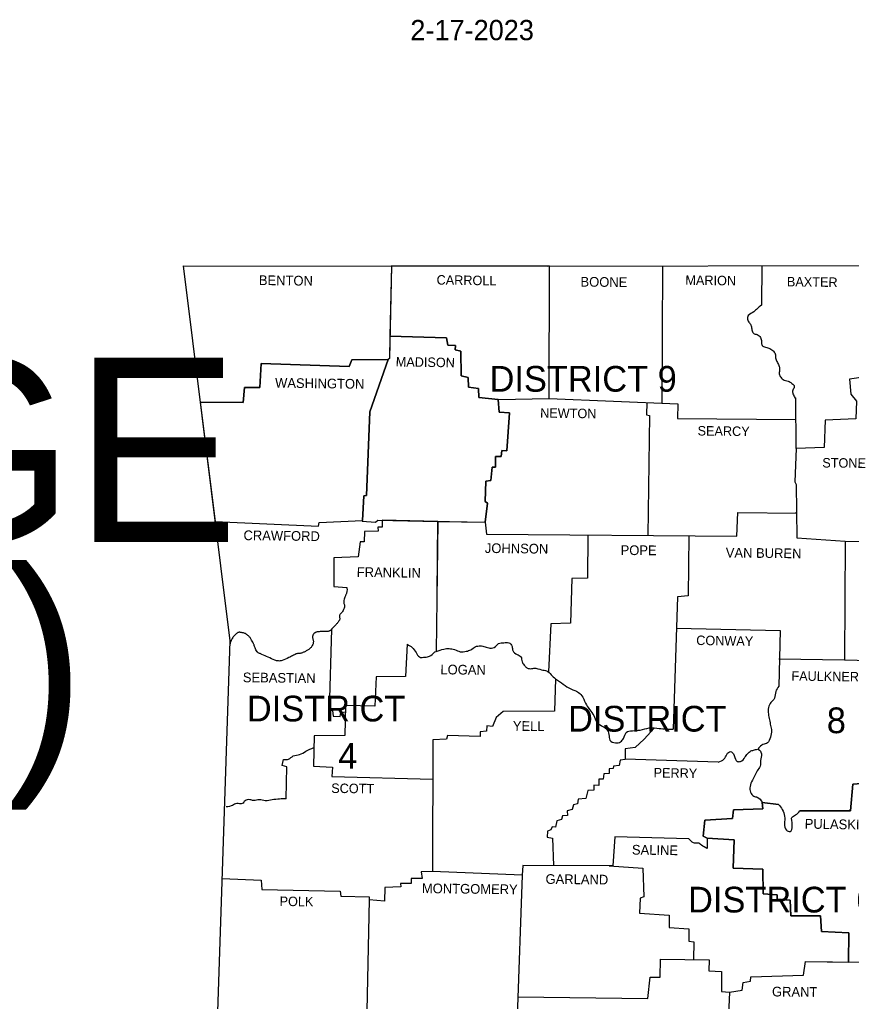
# Model space of a CAD drawing. Extents: x -24122 to 24238, y -8840 to 11381.
# Drawn here: x 10036 to 13643, y 7122 to 11381 of the extents above; entities that cross this region are included whole.
import ezdxf

# ---------------------------------------------------------------- set-up
doc = ezdxf.new("R2010")
doc.units = 0
for name, color, linetype in [('R_Annotation', 7, 'Continuous'), ('R_Border', 7, 'Continuous'), ('R_Grid', 7, 'Continuous'), ('R_No Plot', 7, 'Continuous'), ('S_AREA_CALC', 7, 'Continuous')]:
    doc.layers.add(name, color=color, linetype=linetype)

msp = doc.modelspace()

# ---------------------------------------------------------------- linework, layer by layer
at = {"layer": 'R_Annotation'}
for p, q in [((11648.6, 10312.4), (11641.8, 10007.9)), ((12332.4, 9737.7), (12334.4, 10312)), ((11641.8, 10007.9), (11639.7, 9910.9)), ((11925.3, 9948), (11926.3, 9967.6)), ((11634.8, 9906), (11555.5, 9679)), ((11639.7, 9910.9), (11634.8, 9906)), ((11010.5, 9784.6), (11005.6, 9720.1)), ((11005.6, 9720.1), (10819.1, 9721.1)), ((10819.1, 9721.1), (10883.4, 9204.6)), ((12111.1, 9733), (12028.1, 9741.6)), ((13398.8, 9740.6), (13402.7, 9740.6)), ((11555.5, 9679), (11539.9, 9316)), ((11522.4, 9208.5), (11528.1, 9315)), ((10883.4, 9204.6), (11332.4, 9183.9)), ((11332.4, 9183.9), (11334.4, 9199.6)), ((11334.4, 9199.6), (11522.4, 9208.5)), ((11522.4, 9208.5), (11522.2, 9205.4)), ((11522.2, 9205.4), (11580, 9200.5)), ((11846.2, 8890.8), (11850, 9204.4)), ((11850, 9204.5), (11850, 9204.4)), ((11850, 9204.4), (12055.5, 9200.5)), ((13241.3, 8220.2), (13240.3, 8215.3)), ((13257, 7986.3), (13257, 7984.4)), ((13018.2, 7830.8), (13018.2, 7785.8)), ((13169.9, 7170.3), (13173.8, 7203.6)), ((13173.8, 7203.6), (13206.1, 7209.5)), ((13206.1, 7209.5), (13208, 7229)), ((13115.1, 7162.5), (13169.9, 7170.3))]:
    msp.add_line(p, q, dxfattribs=at)
for points in [[(12334.4, 10312), (12327.5, 10312), (11648.6, 10312.4)], [(11641.8, 10007.9), (11887.2, 9999.9), (11893.1, 9968.6), (11926.3, 9967.6), (11925.3, 9948), (11948.8, 9942.2), (11950.8, 9835.5), (11981.1, 9828.7), (11983.1, 9786.6), (12026.1, 9780.7), (12028.1, 9741.6), (12111.1, 9733), (12113.2, 9732.8), (12332.4, 9737.7)], [(11926.3, 9967.6), (11893.1, 9968.6), (11887.2, 9999.9), (11641.8, 10007.9)], [(11950.8, 9835.5), (11948.8, 9942.2), (11925.3, 9948)], [(11634.8, 9906), (11477.2, 9905), (11465.5, 9875.6), (11083.9, 9889.3), (11078, 9784.6), (11010.5, 9784.6)], [(11528.1, 9315), (11539.9, 9316), (11555.5, 9679), (11634.8, 9906)], [(11983.1, 9786.6), (11981.1, 9828.7), (11950.8, 9835.5)], [(12028.1, 9741.6), (12026.1, 9780.7), (11983.1, 9786.6)], [(12055.5, 9200.5), (12065.3, 9283.7), (12055.5, 9290.6), (12058.4, 9378.6), (12079.9, 9381.5), (12084.8, 9439.3), (12099.5, 9440.2), (12100.5, 9485.3), (12124, 9485.3), (12127.9, 9511.7), (12148.4, 9510.7), (12160.2, 9675.1), (12115.2, 9678), (12111.1, 9733)], [(11539.9, 9316), (11528.1, 9315), (11522.4, 9208.5)], [(11580, 9200.5), (11588.8, 9209.3), (11850, 9204.5)], [(11850, 9204.4), (11608.3, 9209)], [(13419.4, 7948.2), (13639.5, 7949.2), (13649.3, 8064.6), (13780.4, 8074.4)], [(13018.2, 7830.8), (13000.6, 7839.6), (13007.5, 7908.1), (13127.8, 7914.9), (13131.7, 7953.1), (13259.9, 7958), (13257, 7984.4), (13327.4, 7976.6)], [(12938, 7826.9), (12618.1, 7836.6), (12609.3, 7710.4), (12593.6, 7710.5)], [(13631.7, 7292.5), (13632.7, 7419.8), (13513.3, 7425.7), (13509.4, 7493.2), (13380.2, 7493.2), (13378.3, 7561.7), (13321.5, 7565.6), (13321.5, 7584.2), (13260.9, 7589.1), (13258.9, 7695.8), (13130.7, 7700.6), (13134.7, 7822.9), (13018.2, 7830.8)], [(13631.7, 7292.5), (13632.7, 7419.8), (13513.3, 7425.7), (13509.4, 7493.2), (13380.2, 7493.2), (13378.3, 7561.7), (13321.5, 7565.6), (13321.5, 7584.2), (13260.9, 7589.1), (13258.9, 7695.8), (13130.7, 7700.6), (13134.7, 7822.9), (13018.2, 7830.8)], [(12593.6, 7710.5), (12739.4, 7699.7), (12743.3, 7576.4), (12726.7, 7570.5), (12724.7, 7505), (12852.9, 7496.2), (12852.9, 7442.3), (12938, 7437.5), (12939, 7383.6), (12959.5, 7380.7), (12958.5, 7303.4)], [(12958.5, 7303.4), (13027, 7302.4), (13025.1, 7255.5), (13079.9, 7251.6), (13079.9, 7165.5), (13115.1, 7162.5)], [(13208, 7229), (13436, 7235.9), (13444.8, 7295.6), (13631.7, 7292.5)]]:
    msp.add_lwpolyline(points, dxfattribs=at)
for points in [[(13327.4, 7976.6), (13344, 7955), (13353.8, 7925.7), (13353.8, 7892.4), (13361.7, 7865), (13377.3, 7859.1), (13387.1, 7882.6), (13385.1, 7906.1), (13385.1, 7919.8), (13401.8, 7931.5), (13419.4, 7948.2)], [(13018.2, 7785.8), (12992.8, 7800.4), (12978.1, 7809.2), (12962.5, 7808.3), (12949.7, 7816.1), (12938, 7826.9)]]:
    msp.add_spline(points, degree=3, dxfattribs=at)
at = {"layer": 'R_No Plot'}
msp.add_line((11639.7, 9910.9), (11634.8, 9906), dxfattribs=at)
at = {"layer": 'S_AREA_CALC'}
for p, q in [((11836.3, 8638.9), (11843.2, 8639.9)), ((12329.1, 8551.2), (12329.1, 8548.9)), ((11311.9, 8223.1), (11312.3, 8223.3))]:
    msp.add_line(p, q, dxfattribs=at)
for points in [[(10745.4, 10313), (12327.5, 10312), (13715.8, 10314.9), (15353.7, 10340.4), (16112.9, 10358)], [(10745.4, 10313), (10947.9, 8686.9), (10859.9, 6032.5)], [(11648.6, 10312.4), (11639.7, 9910.9)], [(11641.8, 10007.9), (11887.2, 9999.9), (11893.1, 9968.6), (11926.3, 9967.6), (11925.3, 9948), (11948.8, 9942.2), (11950.8, 9835.5), (11981.1, 9828.7), (11983.1, 9786.6), (12026.1, 9780.7), (12028.1, 9741.6), (12113.2, 9732.8), (12332.4, 9737.7), (12334.4, 10312)], [(12824.6, 10313.1), (12821.5, 9717.1)], [(13255.1, 10314), (13253, 10141.8)], [(13715.8, 10314.9), (13717.8, 10076.2), (13701.2, 10075.2), (13704.1, 9831.6), (13635.6, 9821.8), (13641.5, 9756.3), (13665, 9725.9), (13663, 9648.7), (13529.9, 9643.8), (13525, 9524.4), (13403.7, 9520.5), (13397.9, 9375.7), (13404.7, 9363.9), (13407.6, 9133), (13617, 9119.3), (13614.1, 8603.7), (13780.4, 8598.8), (13780.4, 8074.4), (13649.3, 8064.6), (13639.5, 7949.2), (13419.4, 7948.2)], [(10819.1, 9721.1), (11005.6, 9720.1), (11010.5, 9784.6), (11078, 9784.6), (11083.9, 9889.3), (11465.5, 9875.6), (11477.2, 9905), (11634.8, 9906), (11555.5, 9679), (11539.9, 9316), (11528.1, 9315), (11522.2, 9205.4), (11580, 9200.5), (11588.8, 9209.3), (12055.5, 9200.5), (12060.4, 9148.7)], [(12111.1, 9733), (12115.2, 9678), (12160.2, 9675.1), (12148.4, 9510.7), (12127.9, 9511.7), (12124, 9485.3), (12100.5, 9485.3), (12099.5, 9440.2), (12084.8, 9439.3), (12079.9, 9381.5), (12058.4, 9378.6), (12055.5, 9290.6), (12065.3, 9283.7), (12055.5, 9200.5)], [(12332.4, 9737.7), (12890.1, 9714.2), (12889.1, 9650.6), (13403.2, 9646.7)], [(12756.1, 9719.8), (12755, 9666.3), (12767.8, 9663.3), (12759.9, 9143)], [(13403.7, 9520.5), (13402.7, 9740.6)], [(12060.4, 9148.7), (13146.4, 9139.9), (13151.3, 9242.6), (13406.3, 9239.6)], [(13400.8, 9240.7), (13403.7, 9243.6)], [(10883.4, 9204.6), (11332.4, 9183.9), (11334.4, 9199.6), (11522.4, 9208.5)], [(11608.3, 9209), (11608.3, 9179), (11589.8, 9179), (11590.7, 9161.4), (11531.1, 9160.4), (11530.1, 9116.4), (11513.4, 9116.4), (11504.6, 9050.8), (11399, 9046), (11398, 8921.7), (11454.7, 8917.8)], [(11850, 9204.5), (11843.2, 8639.9)], [(12499.7, 9145.1), (12498.7, 8957.9), (12431.2, 8956.9), (12425.3, 8762.2), (12339.2, 8759.3), (12329.1, 8551.2)], [(12938, 9141.6), (12936, 8881.6), (12889.1, 8877.7), (12870.5, 8302.4)], [(13617, 9119.3), (14119.9, 9116.4), (14163, 9136.9), (14160, 8754.4), (14130.7, 8741.7), (14104.3, 8719.2), (14095.5, 8710.4), (14094.5, 8600.8), (13780.4, 8598.8)], [(11388.6, 8736.6), (11378.4, 8387.5), (11393.1, 8383.6), (11396, 8360.1), (11425.4, 8358.1), (11428.3, 8374.8), (11451.8, 8378.7)], [(12884.7, 8741.7), (13334.3, 8730.9), (13328.4, 8489.2)], [(11716.9, 8671.2), (11710.1, 8531.3), (11582.9, 8530.3), (11576.1, 8403.1), (11449.8, 8406.1), (11445.9, 8275), (11313.8, 8274), (11309.9, 8142.9), (11393.1, 8138), (11390.2, 8097.9), (11827.9, 8085.8)], [(13329.4, 8607.6), (13614.1, 8603.7)], [(12359.8, 8521.5), (12355.8, 8380.6), (12132.8, 8379.7), (12103.4, 8354.2), (12086.8, 8315.1), (12062.3, 8317), (12061.3, 8294.5), (12033, 8291.6), (12034, 8271.1), (11892.1, 8275), (11887.2, 8259.3), (11828.5, 8257.4), (11826.5, 7685), (11777.6, 7684), (11781.5, 7654.7), (11734.6, 7655.6), (11733.6, 7634.1), (11687.6, 7634.1), (11688.6, 7618.5), (11620.1, 7616.5), (11619.1, 7556.8), (11552.6, 7562.7), (11541.8, 7081.3)], [(12787.9, 8307.5), (12744.3, 8260.3), (12706.1, 8224.1), (12662.1, 8217.2), (12662.1, 8171.3), (12640.6, 8168.3), (12636.7, 8144.8), (12612.2, 8142.9), (12610.2, 8132.1), (12593.6, 8131.1), (12592.6, 8110.6), (12569.1, 8109.6), (12567.2, 8086.1), (12547.6, 8086.1), (12548.6, 8058.7), (12527.1, 8060.7), (12526.1, 8039.2), (12499.7, 8037.2), (12491.8, 8002), (12458.6, 7999.1), (12455.6, 7979.5), (12438, 7974.6), (12433.1, 7954), (12410.6, 7949.2), (12412.6, 7928.6), (12390.1, 7926.7), (12386.2, 7911), (12365.6, 7905.1), (12360.7, 7878.7), (12345.1, 7879.7), (12340.2, 7866), (12325.5, 7861.1), (12324.5, 7834.7), (12347, 7830.8), (12351.1, 7711.7)], [(11191.5, 8001), (11194.5, 8139), (11174.9, 8144.8), (11180.8, 8171.3)], [(13066.2, 8159.5), (12662.1, 8172.3)], [(13327.4, 7976.6), (13257, 7984.4), (13259.9, 7958), (13131.7, 7953.1), (13127.8, 7914.9), (13007.5, 7908.1), (13000.6, 7839.6), (13018.2, 7830.8), (13018.2, 7785.8)], [(13634.6, 7950.1), (13639.5, 7955)], [(12938, 7826.9), (12618.1, 7836.6), (12609.3, 7710.4), (12217.9, 7712.4), (12215.9, 7670.3)], [(13018.2, 7830.2), (13134.7, 7822.9), (13130.7, 7700.6), (13258.9, 7695.8), (13260.9, 7589.1), (13321.5, 7584.2), (13321.5, 7565.6), (13378.3, 7561.7), (13380.2, 7493.2), (13509.4, 7493.2), (13513.3, 7425.7), (13632.7, 7419.8), (13631.7, 7292.5)], [(12593.6, 7710.5), (12739.4, 7699.7), (12743.3, 7576.4), (12726.7, 7570.5), (12724.7, 7505), (12852.9, 7496.2), (12852.9, 7442.3), (12938, 7437.5), (12939, 7383.6), (12959.5, 7380.7), (12958.5, 7303.4)], [(12215.9, 7670.3), (11826.5, 7685)], [(12215.9, 7670.3), (12193.3, 7056.2)], [(10913.7, 7654.7), (11082.9, 7648.8), (11086.9, 7607.7), (11425.4, 7600.8), (11429.3, 7579.3), (11552.6, 7575.4), (11551.6, 7556.8)], [(12196.4, 7142), (12759.9, 7134.1), (12770.7, 7227.1), (12814.7, 7227.1), (12815.7, 7305.4), (13027, 7302.4), (13025.1, 7255.5), (13079.9, 7251.6), (13079.9, 7165.5), (13115.1, 7162.5)], [(13115.1, 7162.5), (13169.9, 7170.3), (13173.8, 7203.6), (13206.1, 7209.5), (13208, 7229), (13436, 7235.9), (13444.8, 7295.6), (13678.7, 7291.7)], [(13115.1, 7162.5), (13103.4, 6906.2), (13094.5, 6909.1), (13095.5, 6776)]]:
    msp.add_lwpolyline(points, dxfattribs=at)
for points in [[(13253, 10141.8), (13235.4, 10127.1), (13219.8, 10113.4), (13196.3, 10096.8), (13193.4, 10081.1), (13201.2, 10065.5), (13209, 10052.7), (13212, 10035.1), (13218.8, 10020.4), (13235.4, 10014.6), (13249.1, 10001.9), (13254, 9984.2), (13256, 9967.6), (13271.6, 9959.8), (13289.2, 9953.9), (13305.9, 9942.2), (13313.7, 9927.5), (13315.7, 9908.9), (13322.5, 9894.2), (13330.3, 9876.6), (13332.3, 9861.9), (13330.3, 9847.3), (13334.3, 9833.6), (13347, 9819.9), (13369.5, 9813), (13385.1, 9803.2), (13395.9, 9789.5), (13389, 9772.9), (13390, 9758.2), (13398.8, 9740.6)], [(11454.7, 8917.8), (11455.6, 8912.7), (11456, 8907.5), (11454.7, 8897.2), (11453, 8891.8), (11450.9, 8886.5), (11448.8, 8881.1), (11446.9, 8875.7), (11442, 8857.1), (11442, 8851.1), (11443.5, 8844.9), (11445, 8838.8), (11445.3, 8835.7), (11445, 8832.7), (11441.3, 8822.6), (11436.1, 8813.1), (11433.1, 8809), (11429.7, 8805.2), (11426.2, 8801.5), (11423.4, 8797.4), (11422.6, 8792.8), (11423.5, 8787.7), (11424.3, 8782.5), (11423.4, 8777.9), (11421.9, 8775.1), (11420.2, 8772.4), (11416.8, 8767.1), (11413, 8762.1), (11408.8, 8757.3), (11393.1, 8741.7), (11386.9, 8734.6), (11383.5, 8731.4), (11381.6, 8730), (11380.5, 8729.5), (11379.4, 8728.9), (11373.4, 8727.3), (11367.2, 8726.9), (11361.1, 8727), (11358, 8727.1), (11354.9, 8727), (11344.7, 8726.5), (11334.4, 8726), (11329.1, 8725.5), (11323.9, 8724.4), (11318.8, 8722.4), (11316.3, 8720.9), (11313.8, 8719.2), (11310.6, 8715.9), (11308.4, 8712.3), (11306.9, 8708.5), (11306, 8704.5), (11306.3, 8698.9), (11307.9, 8693.2), (11309.6, 8687.6), (11309.9, 8682), (11309, 8676.4), (11307.6, 8671), (11302.1, 8660.5), (11292.5, 8651), (11281.6, 8643.8), (11270.5, 8637.8), (11259.1, 8633.1), (11253.2, 8631.8), (11247.2, 8631.4), (11241.2, 8630.8), (11235.6, 8629.2), (11227.4, 8625.4), (11219.4, 8621.4), (11211.4, 8617.4), (11203.3, 8613.5), (11173.9, 8600.8), (11166.3, 8599), (11158.2, 8598.8), (11150.2, 8600.2), (11142.6, 8602.7), (11113.3, 8615.5), (11086.9, 8627.2), (11081.4, 8629.5), (11075.9, 8631.9), (11070.8, 8634.9), (11068.4, 8636.8), (11067.3, 8637.8), (11066.3, 8638.9), (11060.8, 8647.4), (11056.9, 8656.6), (11053.6, 8666), (11051.8, 8670.6), (11049.7, 8675.1), (11044.5, 8685), (11038.9, 8694.7), (11035.2, 8700.3), (11030.9, 8705.3), (11026, 8709.9), (11023.2, 8712.1), (11020.3, 8714.3), (11014.9, 8717.4), (11009.3, 8719.5), (11003.6, 8721), (10997.8, 8722.1), (10993.2, 8722.9), (10988.5, 8723.2), (10983.7, 8722.4), (10981.4, 8721.5), (10979.2, 8720.1), (10967.2, 8709.2), (10958.2, 8697.1), (10951.7, 8684), (10949.3, 8677.1), (10947.4, 8670.1)], [(11716.9, 8671.2), (11738.5, 8657.5), (11755.1, 8635), (11769.8, 8616.4), (11794.2, 8615.5), (11813.8, 8619.4), (11836.3, 8638.9)], [(11843.2, 8639.9), (11875.5, 8650.7), (11898.9, 8652.6), (11922.4, 8648.7), (11946.9, 8638.9), (11973.3, 8640.9), (11992.9, 8647.7), (12012.4, 8660.5), (12034, 8664.4), (12054.5, 8660.5), (12076, 8654.6), (12099.5, 8661.4), (12113.2, 8674.2), (12136.7, 8678.1), (12157.2, 8678.1), (12171.9, 8661.4), (12174.8, 8643.8), (12193.4, 8627.2), (12210.1, 8616.4), (12215, 8595.9), (12223.8, 8581.2), (12232.6, 8571.4), (12245.3, 8565.6), (12266.8, 8567.5), (12300.1, 8560.7), (12321.6, 8555.8), (12341.2, 8539.1), (12359.8, 8521.5)], [(12359.8, 8521.5), (12394, 8498), (12426.3, 8477.5), (12459.6, 8462.8), (12478.1, 8441.3), (12494.8, 8408), (12508.5, 8387.5), (12526.1, 8362), (12538.8, 8333.7), (12559.4, 8318), (12580.9, 8304.3), (12591.6, 8279.9), (12596.5, 8255.4), (12620, 8243.7), (12642.5, 8248.5), (12655.2, 8263.2), (12667, 8288.7), (12693.4, 8296.5), (12727.6, 8299.4), (12766.8, 8308.2), (12809.8, 8306.3), (12870.5, 8302.4)], [(13328.4, 8489.2), (13315.7, 8466.7), (13309.8, 8437.4), (13294.1, 8418.8), (13284.4, 8397.3), (13283.4, 8368.9), (13288.3, 8343.5), (13293.2, 8319), (13297.1, 8296.5), (13292.2, 8268.1), (13279.5, 8243.7), (13259.9, 8236.8), (13241.3, 8220.2)], [(11180.8, 8171.3), (11202.3, 8173.2), (11222.9, 8186.9), (11250.2, 8192.8), (11277.6, 8207.5), (11311.9, 8223.1)], [(13066.2, 8159.5), (13090.6, 8173.2), (13103.4, 8193.8), (13119, 8206.5), (13134.7, 8188.9), (13148.4, 8163.4), (13163, 8163.4), (13181.6, 8181), (13193.4, 8196.7), (13208, 8208.4), (13223.7, 8213.3), (13240.3, 8215.3), (13253, 8196.7), (13249.1, 8167.3), (13249.1, 8147.8), (13238.4, 8127.2), (13226.6, 8105.7), (13213.9, 8081.2), (13204.1, 8054.8), (13206.1, 8029.4), (13219.8, 8012.8), (13235.4, 8007.9), (13257, 7986.3)], [(11191.5, 8001), (11163.2, 8000), (11130.9, 7996.1), (11101.5, 7992.2), (11075.1, 7997.1), (11050.7, 7993.2), (11034, 7997.1), (11013.5, 7992.2), (11001.7, 7980.5), (10977.3, 7980.5), (10959.7, 7972.6), (10931.3, 7965.8)], [(13327.4, 7976.6), (13344, 7955), (13353.8, 7925.7), (13353.8, 7892.4), (13361.7, 7865), (13377.3, 7859.1), (13387.1, 7882.6), (13385.1, 7906.1), (13385.1, 7919.8), (13401.8, 7931.5), (13419.4, 7948.2)], [(13018.2, 7785.8), (12992.8, 7800.4), (12978.1, 7809.2), (12962.5, 7808.3), (12949.7, 7816.1), (12938, 7826.9)]]:
    msp.add_spline(points, degree=3, dxfattribs=at)

# ---------------------------------------------------------------- texts
at = {"layer": 'R_Border'}
for s, height, p in [('2-17-2023', 87.92, (11730.5, 11291.7)), ('HYDRODEMOLITION BRIDGE', 800, (-3934, 9114.5)), ('PRESERVATION (2023) (S)', 800, (-3171.8, 8194.8))]:
    msp.add_text(s, height=height, dxfattribs=at).set_placement(p)
for s, height, rotation, p in [('BENTON', 42.07, 359.2527, (11073.2, 10229.8)), ('CARROLL', 41.09, 359.1481, (11844.1, 10231.8)), ('BOONE', 42.07, 359.4001, (12468.4, 10223)), ('MARION', 41.09, 359.1854, (12923.3, 10230.8)), ('BAXTER', 41.09, 359.2559, (13363.6, 10224)), ('MADISON', 41.09, 359.0906, (11667, 9876.6)), ('WASHINGTON', 42.06, 359.232, (11143.6, 9784.6)), ('NEWTON', 41.09, 359.2717, (12293.2, 9654.5)), ('SEARCY', 41.08, 359.2527, (12976.2, 9577.2)), ('STONE', 41.08, 359.4001, (13517.2, 9438.3)), ('CRAWFORD', 42.06, 359.2771, (11006.6, 9123.2)), ('JOHNSON', 42.07, 359.3514, (12053.5, 9067.5)), ('POPE', 42.07, 359.6155, (12642.5, 9058.7)), ('VAN BUREN', 42.07, 359.3508, (13098.5, 9047.9)), ('FRANKLIN', 42.07, 359.1815, (11497.8, 8963.8)), ('CONWAY', 41.08, 359.0371, (12970.3, 8668.3)), ('LOGAN', 42.07, 359.3969, (11860.8, 8541.1)), ('SEBASTIAN', 42.06, 359.2816, (11003.7, 8506.8)), ('FAULKNER', 41.09, 359.2486, (13383.2, 8513.7)), ('YELL', 42.07, 359.1987, (12174.8, 8296.5)), ('PERRY', 41.09, 359.0858, (12785.4, 8094)), ('SCOTT', 41.09, 359.4063, (11387.2, 8026.5)), ('PULASKI', 42.07, 359.053, (13440.9, 7871.9)), ('SALINE', 42.07, 359.1491, (12691.4, 7759.3)), ('GARLAND', 42.07, 359.3658, (12316.7, 7632.2)), ('MONTGOMERY', 42.07, 359.2944, (11780.5, 7592)), ('POLK', 41.08, 359.2152, (11163.2, 7536.3)), ('GRANT', 42.07, 359.4032, (13299, 7143.9))]:
    msp.add_text(s, height=height, rotation=rotation, dxfattribs=at).set_placement(p)
at = {"layer": 'R_Grid'}
for s, height, p in [('DISTRICT 9', 111.54, (12074.1, 9767)), ('DISTRICT', 111.54, (11021.3, 8336.6)), ('DISTRICT', 111.54, (12414.6, 8292.6)), ('8', 111.5, (13536.8, 8285.7)), ('4', 111.5, (11417.6, 8131.1)), ('DISTRICT 6', 111.54, (12935.1, 7507.9))]:
    msp.add_text(s, height=height, dxfattribs=at).set_placement(p)

doc.saveas('drawing.dxf')
